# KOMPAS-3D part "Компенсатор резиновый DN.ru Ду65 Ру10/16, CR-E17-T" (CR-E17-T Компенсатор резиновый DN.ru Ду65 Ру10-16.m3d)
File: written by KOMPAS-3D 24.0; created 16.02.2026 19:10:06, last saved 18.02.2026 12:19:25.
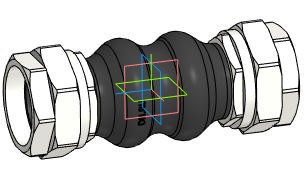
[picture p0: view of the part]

Document properties: Автор: DN.RU; Полное имя файла: CR-E17-T Компенсатор резиновый DN.ru Ду65 Ру10-16.cdw

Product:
- Body: Твердое тело1  | qty 1
    Масса: 5.04771
- Part/product: Компенсатор резиновый DN.ru Ду65 Ру10/16  | designation CR-E17-T
    Масса: 2.2
    Раздел спецификации: Прочие изделия
    Форматы листов документа: A3
    Комментарий: D140-02404
    Примечание: D140-02404
    additional columns: Типовые

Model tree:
1. Твердое тело1  (labels: Твердое тело1)

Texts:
  CR-E17-T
